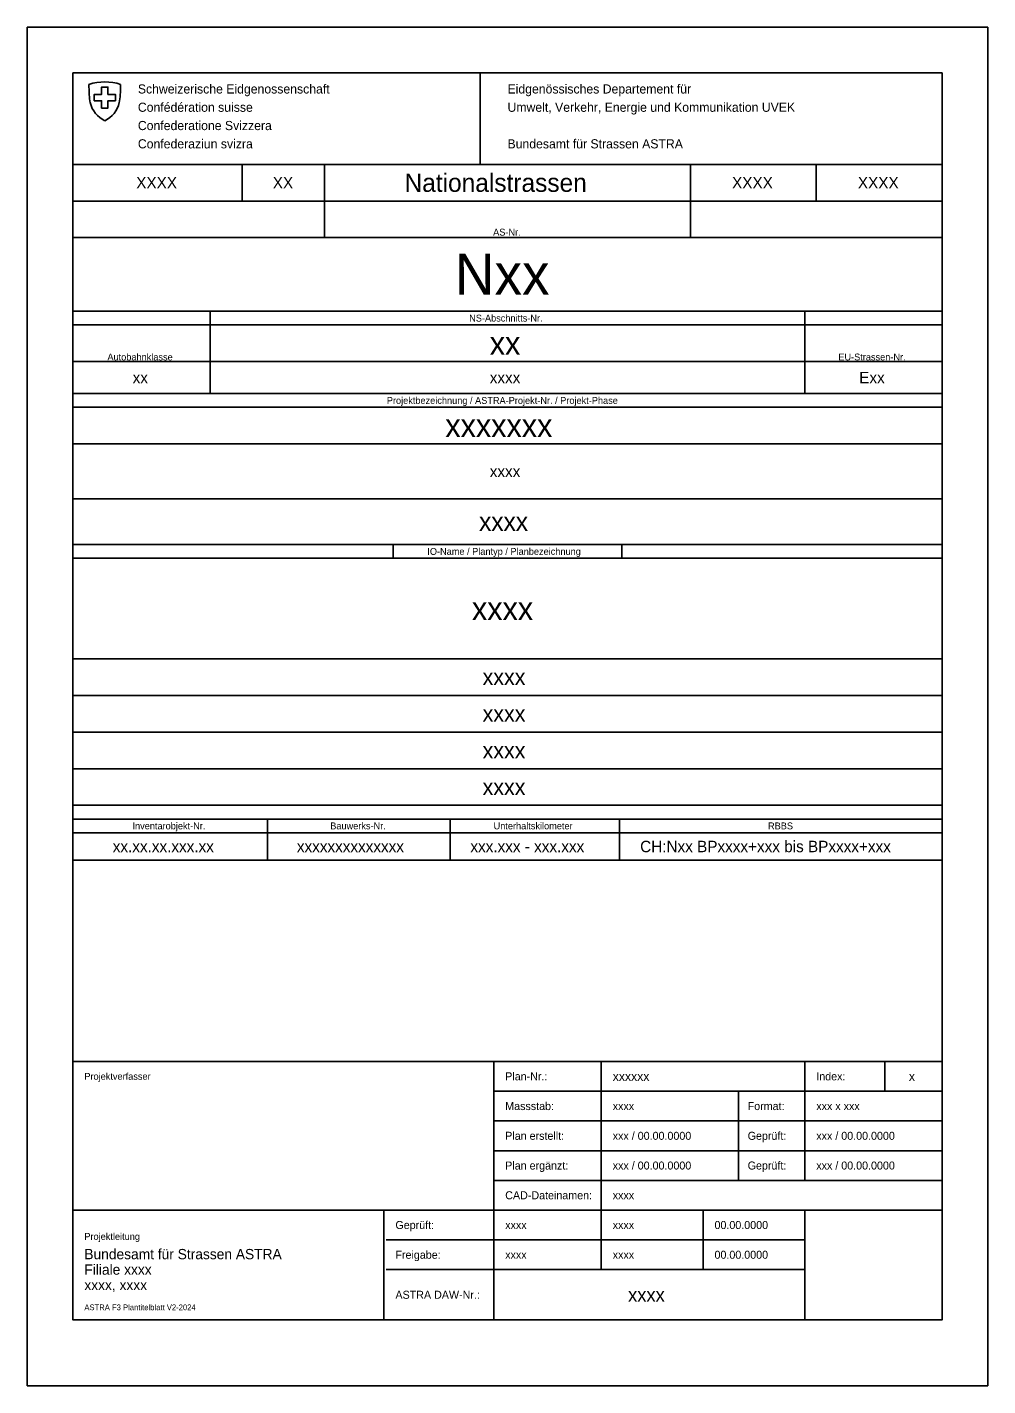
# Model space of a CAD drawing. Extents: x 0 to 443, y 0 to 297.
# Drawn here: x 0 to 210, y 0 to 297 of the extents above; entities that cross this region are included whole.
import ezdxf

# ---------------------------------------------------------------- set-up
doc = ezdxf.new("R2010")
doc.units = 0
doc.layers.add('A_Titel', color=7, linetype='Continuous')
doc.layers.add('HILFSKONSTR', color=7, linetype='Continuous')

msp = doc.modelspace()

# ---------------------------------------------------------------- linework, layer by layer
at = {"layer": 'A_Titel'}
for p, q in [((10, 267), (200, 267)), ((47, 259), (47, 267)), ((172.5, 259), (172.5, 267)), ((10, 216.9), (200, 216.9)), ((10, 193.9), (200, 193.9)), ((10, 183.9), (200, 183.9)), ((10, 114.9), (200, 114.9)), ((10, 70.9), (200, 70.9)), ((125.5, 25.4), (125.5, 70.9)), ((170, 44.9), (170, 70.9)), ((187.5, 64.4), (187.5, 70.9)), ((102, 64.4), (200, 64.4)), ((155.5, 44.9), (155.5, 64.4)), ((102, 57.9), (200, 57.9)), ((102, 51.4), (200, 51.4)), ((102, 44.9), (200, 44.9)), ((10, 38.4), (102, 38.4)), ((78, 14.4), (78, 38.4)), ((102, 38.4), (200, 38.4)), ((147.75, 25.4), (147.75, 38.4)), ((170, 14.4), (170, 38.4)), ((78.5, 31.9), (170, 31.9)), ((78.5, 25.4), (170, 25.4))]:
    msp.add_line(p, q, dxfattribs=at)
for points in [[(0, 297), (210, 297), (210, 0), (0, 0)], [(10, 287), (200, 287), (200, 14.4), (10, 14.4)], [(10, 267), (65, 267), (65, 259), (10, 259)], [(145, 267), (200, 267), (200, 259), (145, 259)], [(10, 193.9), (200, 193.9), (200, 183.9), (10, 183.9)]]:
    msp.add_lwpolyline(points, close=True, dxfattribs=at)
for points in [[(19.28, 281.61), (19.28, 280.91), (17.66, 280.91), (17.66, 279.3), (16.27, 279.3), (16.27, 280.91), (14.66, 280.91), (14.66, 282.3), (16.27, 282.3), (16.27, 283.92), (16.96, 283.92), (17.66, 283.92), (17.66, 282.3), (19.28, 282.3), (19.28, 281.61)], [(19.28, 281.61), (19.28, 280.91), (17.66, 280.91), (17.66, 279.3), (16.27, 279.3), (16.27, 280.91), (14.66, 280.91), (14.66, 282.3), (16.27, 282.3), (16.27, 283.92), (16.96, 283.92), (17.66, 283.92), (17.66, 282.3), (19.28, 282.3), (19.28, 281.61)], [(102, 14.4), (102, 70.9)]]:
    msp.add_lwpolyline(points, dxfattribs=at)
for centre, radius, start, end in [((16.96, 273.48), 11.55, 72.5424, 107.4576), ((16.96, 273.48), 11.55, 72.5424, 107.4576), ((53.54, 284.5), 40.04, 180, 183.3074), ((53.54, 284.5), 40.04, 180, 183.3074), ((21.65, 282.42), 8.08, 181.6543, 193.7917), ((21.65, 282.42), 8.08, 181.6543, 193.7917), ((12.28, 282.42), 8.08, 346.2086, 358.3461), ((12.28, 282.42), 8.08, 346.2086, 358.3461), ((-19.61, 284.5), 40.04, 356.6926, 0), ((-19.61, 284.5), 40.04, 356.6926, 0), ((19.43, 281.77), 5.77, 192.7171, 244.7356), ((19.43, 281.77), 5.77, 192.7171, 244.7356), ((14.5, 281.77), 5.77, 295.2643, 347.2828), ((14.5, 281.77), 5.77, 295.2643, 347.2828)]:
    msp.add_arc(centre, radius, start, end, dxfattribs=at)
at = {"layer": 'HILFSKONSTR'}
for p, q in [((10, 259), (200, 259)), ((65, 259), (65, 251)), ((145, 259), (145, 251)), ((200, 251), (10, 251)), ((10, 234.9), (200, 234.9)), ((40, 234.9), (40, 216.9)), ((170, 234.9), (170, 216.9)), ((10, 231.9), (200, 231.9)), ((10, 223.9), (200, 223.9)), ((10, 213.9), (200, 213.9)), ((10, 205.9), (200, 205.9)), ((80, 183.9), (80, 180.9)), ((130, 180.9), (130, 183.9)), ((10, 180.9), (200, 180.9)), ((10, 158.9), (200, 158.9)), ((10, 150.9), (200, 150.9)), ((10, 142.9), (200, 142.9)), ((10, 134.9), (200, 134.9)), ((10, 126.9), (200, 126.9)), ((10, 123.9), (200, 123.9)), ((52.5, 123.9), (52.5, 114.92)), ((92.5, 123.9), (92.5, 114.92)), ((129.5, 123.9), (129.5, 114.9)), ((10, 120.9), (200, 120.9))]:
    msp.add_line(p, q, dxfattribs=at)
msp.add_lwpolyline([(99, 287), (99, 267)], dxfattribs=at)

# ---------------------------------------------------------------- texts
at = {"layer": 'A_Titel'}
for s, height, p in [('Schweizerische Eidgenossenschaft', 2, (24.2, 282.5)), ('Eidgenössisches Departement für', 2, (105, 282.5)), ('Confédération suisse', 2, (24.2, 278.5)), ('Umwelt, Verkehr, Energie und Kommunikation UVEK', 2, (105, 278.5)), ('Confederatione Svizzera', 2, (24.2, 274.5)), ('Confederaziun svizra', 2, (24.2, 270.5)), ('Bundesamt für Strassen ASTRA', 2, (105, 270.5)), ('Nationalstrassen', 4, (82.49, 261)), ('XXXX', 2.5, (23.84, 261.75)), ('XX', 2.5, (53.69, 261.75)), ('XXXX', 2.5, (154.09, 261.75)), ('XXXX', 2.5, (181.59, 261.75)), ('AS-Nr.', 1.5, (101.86, 251.44)), ('Nxx', 9, (93.47, 238.5)), ('NS-Abschnitts-Nr.', 1.5, (96.62, 232.65)), ('xx', 5, (101.12, 225.4)), ('Autobahnklasse', 1.5, (17.54, 224.15)), ('EU-Strassen-Nr.', 1.5, (177.32, 224.15)), ('xx', 2.5, (23.06, 219.15)), ('xxxx', 2.5, (101.12, 219.15)), ('Exx', 2.5, (181.89, 219.15)), ('Projektbezeichnung / ASTRA-Projekt-Nr. / Projekt-Phase', 1.5, (78.62, 214.65)), ('xxxxxxx', 5, (91.41, 207.4)), ('xxxx', 2.5, (101.12, 198.65)), ('xxxx', 4, (98.79, 186.9)), ('IO-Name / Plantyp / Planbezeichnung', 1.5, (87.47, 181.65)), ('xxxx', 5, (97.23, 167.4)), ('xxxx', 3.5, (99.56, 153.2)), ('xxxx', 3.5, (99.56, 145.2)), ('xxxx', 3.5, (99.56, 137.15)), ('xxxx', 3.5, (99.56, 129.15)), ('Inventarobjekt-Nr.', 1.5, (23.02, 121.65)), ('Bauwerks-Nr.', 1.5, (66.25, 121.65)), ('Unterhaltskilometer', 1.5, (101.96, 121.65)), ('RBBS', 1.5, (161.95, 121.65)), ('CH:Nxx BPxxxx+xxx bis BPxxxx+xxx', 2.5, (134, 116.65)), ('xx.xx.xx.xxx.xx', 2.5, (18.71, 116.65)), ('xxxxxxxxxxxxxx', 2.5, (58.96, 116.65)), ('xxx.xxx - xxx.xxx', 2.5, (96.89, 116.65)), ('Projektverfasser', 1.5, (12.5, 66.9)), ('Plan-Nr.:', 1.75, (104.5, 66.78)), ('Index:', 1.75, (172.5, 66.78)), ('xxxxxx', 2, (128, 66.65)), ('x', 2, (192.74, 66.65)), ('Massstab:', 1.75, (104.5, 60.28)), ('xxxx', 1.75, (128, 60.28)), ('Format:', 1.75, (157.5, 60.28)), ('xxx x xxx', 1.75, (172.5, 60.28)), ('Plan erstellt:', 1.75, (104.5, 53.78)), ('xxx / 00.00.0000', 1.75, (128, 53.78)), ('Geprüft:', 1.75, (157.5, 53.78)), ('xxx / 00.00.0000', 1.75, (172.5, 53.78)), ('Plan ergänzt:', 1.75, (104.5, 47.28)), ('xxx / 00.00.0000', 1.75, (128, 47.28)), ('Geprüft:', 1.75, (157.5, 47.28)), ('xxx / 00.00.0000', 1.75, (172.5, 47.28)), ('CAD-Dateinamen:', 1.75, (104.5, 40.78)), ('xxxx', 1.75, (128, 40.78)), ('Geprüft:', 1.75, (80.5, 34.28)), ('00.00.0000', 1.75, (150.25, 34.28)), ('Projektleitung', 1.5, (12.5, 31.9)), ('xxxx', 1.75, (104.5, 34.28)), ('xxxx', 1.75, (128, 34.28)), ('Bundesamt für Strassen ASTRA', 2.25, (12.5, 27.67)), ('Freigabe:', 1.75, (80.5, 27.78)), ('xxxx', 1.75, (104.5, 27.78)), ('xxxx', 1.75, (128, 27.78)), ('00.00.0000', 1.75, (150.25, 27.78)), ('Filiale xxxx', 2.25, (12.5, 24.29)), ('xxxx, xxxx', 2.25, (12.5, 20.92)), ('ASTRA DAW-Nr.:', 1.75, (80.5, 19.03)), ('ASTRA F3 Plantitelblatt V2-2024', 1.25, (12.5, 16.53)), ('xxxx', 3, (131.36, 18.4))]:
    msp.add_text(s, height=height, dxfattribs=at).set_placement(p)

doc.saveas('drawing.dxf')
